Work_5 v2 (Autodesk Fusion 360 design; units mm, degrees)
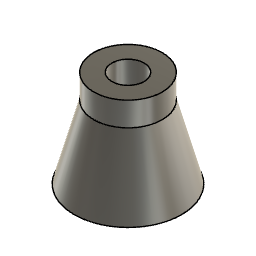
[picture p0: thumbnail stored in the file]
sketch "Sketch1" plane through (0, 0, 0) normal (0, 1, 0) x axis (1, 0, 0)
  line L1 (30, 30) -> (30, -150)
  line L2 (100, 30) -> (30, 30)
  line L3 (63.7653, -105.2296) -> (100, 30)
  line L4 (63.7653, -150) -> (63.7653, -105.2296)
  line L5 (30, -150) -> (63.7653, -150)
  point P4 (100, 30)
  point P5 (63.7653, -105.2296)
  point P2 (30, -150)
  point P3 (30, 30)
  point P1 (0, 0)
  vertical L1
  perpendicular L1 L2
  perpendicular L2 L4
  perpendicular L1 L5
  dimension "d1" angle L2 L3 = 75
  dimension "d2" distance P4 P5 = 140
  dimension "d3" distance P2 P3 = 180
  dimension "d4" distance P3 P4 = 70
  dimension "d5" distance P1 L1 = 30
  dimension "d6" distance P1 L2 = 30
revolve "Revolve1" sketch "Sketch1" AlongAngle 360 bodies "Tea Kettle"
named bodies: "Tea Kettle"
